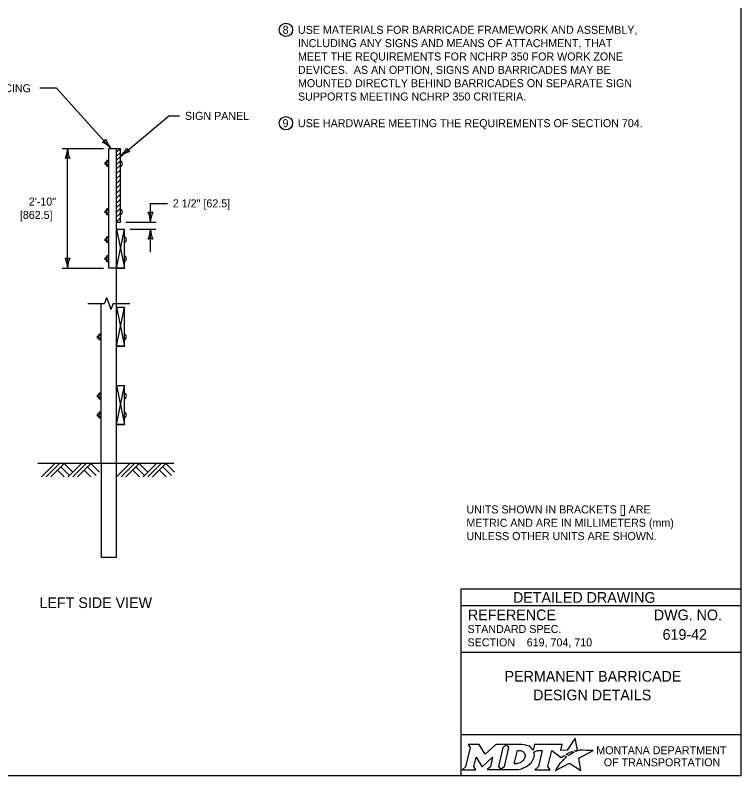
# Model space of a CAD drawing. Extents: x 49991.4 to 50021, y 49987.6 to 50011.4.
# Drawn here: x 50011.31 to 50016.75, y 49987.8 to 49993.5 of the extents above; entities that cross this region are included whole.
import ezdxf

# ---------------------------------------------------------------- set-up
doc = ezdxf.new("R2010")
doc.units = 0
for name, color, linetype in [('Default', 7, 'Continuous'), ('Level 1', 7, 'Continuous'), ('Level 2', 7, 'Continuous'), ('Level 3', 7, 'Continuous'), ('Level 4', 7, 'Continuous'), ('Level 5', 7, 'Continuous'), ('Level 6', 7, 'Continuous')]:
    doc.layers.add(name, color=color, linetype=linetype)

msp = doc.modelspace()

# ---------------------------------------------------------------- linework, layer by layer
at = {"layer": 'Default'}
for points in [[(50015.5126, 49987.9811), (50015.5023, 49987.9867), (50015.5139, 49987.9895), (50015.5255, 49987.9915), (50015.5081, 49988.0816), (50015.4486, 49987.9903), (50015.4013, 49987.9896), (50015.4116, 49988.0337), (50015.2024, 49988.0338), (50015.1923, 49987.9913), (50015.1865, 49987.9996)], [(50014.7056, 49988.0338), (50014.7197, 49988.0104), (50014.6862, 49987.8671), (50014.6605, 49987.8446), (50014.7621, 49987.8446), (50014.7486, 49987.8674), (50014.7648, 49987.9375), (50014.8085, 49987.8685), (50014.8138, 49987.8685), (50014.8889, 49987.938), (50014.8725, 49987.8669), (50014.8478, 49987.8449), (50014.9494, 49987.8449), (50014.9356, 49987.8682), (50014.9688, 49988.0106)], [(50014.9688, 49988.0106), (50014.9941, 49988.0338), (50014.9117, 49988.0338), (50014.8321, 49987.9608), (50014.7876, 49988.0335), (50014.7056, 49988.0338)], [(50015.1077, 49988.0338), (50014.9941, 49988.0338), (50015.0088, 49988.0109), (50014.9749, 49987.8671), (50014.9494, 49987.8449), (50015.06, 49987.8449)], [(50015.1317, 49987.9471), (50015.1305, 49987.939), (50015.1273, 49987.9297), (50015.1231, 49987.9215), (50015.1175, 49987.914), (50015.111, 49987.9071), (50015.1031, 49987.9008), (50015.0948, 49987.8961), (50015.0857, 49987.8922), (50015.0766, 49987.8899), (50015.0674, 49987.889), (50015.0515, 49987.889), (50015.0751, 49987.989), (50015.0911, 49987.989), (50015.0987, 49987.9884), (50015.1063, 49987.9865), (50015.1129, 49987.9835), (50015.119, 49987.9793), (50015.1238, 49987.9743), (50015.1275, 49987.9683), (50015.1302, 49987.9621), (50015.1318, 49987.9547), (50015.1318, 49987.9517), (50015.1317, 49987.9471)], [(50015.3882, 49987.8843), (50015.3729, 49987.8599), (50015.3682, 49987.8524), (50015.3624, 49987.8438), (50015.3601, 49987.8395), (50015.4654, 49987.8926), (50015.5493, 49987.8375), (50015.5362, 49987.9302), (50015.6431, 49987.9886), (50015.5938, 49987.9894), (50015.5637, 49987.9898), (50015.5429, 49987.9901), (50015.5361, 49987.9886), (50015.5312, 49987.9874), (50015.5228, 49987.9851), (50015.5126, 49987.9811)], [(50015.1991, 49987.9747), (50015.2237, 49987.9878), (50015.2606, 49987.9878), (50015.232, 49987.8673), (50015.2045, 49987.8446), (50015.3207, 49987.8446), (50015.3037, 49987.8675), (50015.3319, 49987.9877), (50015.4032, 49987.936), (50015.4243, 49987.9511), (50015.444, 49987.9402)], [(50015.4622, 49987.9535), (50015.4598, 49987.9518), (50015.4415, 49987.9614), (50015.4518, 49987.9671), (50015.4559, 49987.9693), (50015.4645, 49987.9733), (50015.4702, 49987.9759), (50015.4781, 49987.9789), (50015.4854, 49987.9816), (50015.4972, 49987.9742), (50015.4932, 49987.9721), (50015.4886, 49987.9696), (50015.4844, 49987.9674), (50015.4794, 49987.9645), (50015.4775, 49987.9634), (50015.4748, 49987.9618), (50015.4723, 49987.9604), (50015.47, 49987.9588), (50015.4674, 49987.957), (50015.4647, 49987.9552), (50015.4622, 49987.9535)], [(50015.4021, 49987.9004), (50015.4021, 49987.9004)], [(50015.1057, 49987.8522), (50015.1141, 49987.8548), (50015.1271, 49987.8602), (50015.1475, 49987.8712)]]:
    msp.add_lwpolyline(points, dxfattribs=at)
for centre, radius, start, end in [((50015.1308, 49987.9554), 0.0709, 339.5329, 15.8582), ((50015.0868, 49987.9727), 0.1183, 300.9103, 339.1383)]:
    msp.add_arc(centre, radius, start, end, dxfattribs=at)
for centre, major_axis, ratio, start_param, end_param in [((50015.1056, 49987.9864), (0.0834, -0.0037), 0.568097, 0.61298, 1.570796), ((50015.1612, 49987.9937), (0.0361, -0.0295), 0.469099, 1.225588, 1.570796), ((50015.4329, 49987.9305), (-0.0112, -0.0097), 0.021651, 3.157348, 6.283185), ((50015.3952, 49987.8923), (-0.00694, -0.00806), 0.008222, 0, 3.137361), ((50015.4119, 49987.9106), (-0.0098, -0.0102), 0.016458, 3.141593, 6.279097), ((50015.0603, 49987.9932), (0, 0.1484), 0.987302, 3.139398, 3.456847)]:
    msp.add_ellipse(centre, major_axis=major_axis, ratio=ratio, start_param=start_param, end_param=end_param, dxfattribs=at)
at = {"layer": 'Level 1'}
for p, q in [((50012.0102, 49992.5038), (50012.0975, 49992.5038)), ((50012.0102, 49991.6053), (50012.0102, 49992.5038)), ((50012.0687, 49991.8982), (50012.0687, 49992.5038)), ((50012.0975, 49992.5038), (50012.0687, 49992.475)), ((50012.0975, 49991.95), (50012.0975, 49992.5038)), ((50012.0975, 49992.4735), (50012.0687, 49992.4447)), ((50012.0975, 49992.4435), (50012.0687, 49992.4147)), ((50011.9838, 49992.3821), (50011.9838, 49992.3971)), ((50011.9952, 49992.3971), (50011.9838, 49992.3971)), ((50011.9952, 49992.3821), (50011.9838, 49992.3821)), ((50012.0102, 49992.4116), (50011.9952, 49992.4116)), ((50011.9952, 49992.3676), (50011.9952, 49992.4116)), ((50012.0102, 49992.4006), (50011.9952, 49992.4006)), ((50012.0975, 49992.4106), (50012.0687, 49992.3818)), ((50012.0102, 49992.3786), (50011.9952, 49992.3786)), ((50012.0102, 49992.3676), (50011.9952, 49992.3676)), ((50012.0975, 49992.3782), (50012.0687, 49992.3494)), ((50012.0975, 49992.3435), (50012.0687, 49992.3147)), ((50012.0975, 49992.3059), (50012.0687, 49992.2771)), ((50012.0975, 49992.2701), (50012.0687, 49992.2413)), ((50012.0975, 49992.2342), (50012.0687, 49992.2054)), ((50012.0975, 49992.1973), (50012.0687, 49992.1685)), ((50012.0975, 49992.1591), (50012.0687, 49992.1303)), ((50012.0975, 49992.1221), (50012.0687, 49992.0933)), ((50012.0102, 49992.0504), (50011.9952, 49992.0504)), ((50011.9952, 49992.0064), (50011.9952, 49992.0504)), ((50012.0102, 49992.0394), (50011.9952, 49992.0394)), ((50012.0975, 49992.0883), (50012.0687, 49992.0595)), ((50012.0975, 49992.054), (50012.0687, 49992.0252)), ((50011.9838, 49992.0209), (50011.9838, 49992.0359)), ((50011.9952, 49992.0359), (50011.9838, 49992.0359)), ((50011.9952, 49992.0209), (50011.9838, 49992.0209)), ((50012.0102, 49992.0174), (50011.9952, 49992.0174)), ((50012.0102, 49992.0064), (50011.9952, 49992.0064)), ((50012.0975, 49992.0183), (50012.0687, 49991.9895)), ((50012.0975, 49991.9827), (50012.0687, 49991.9539)), ((50012.0687, 49991.95), (50012.0975, 49991.95)), ((50012.0687, 49991.6053), (50012.1273, 49991.8982)), ((50012.0687, 49991.8982), (50012.1273, 49991.6053)), ((50012.0687, 49990.1408), (50012.0687, 49991.8982)), ((50012.0687, 49991.8982), (50012.1273, 49991.8982)), ((50012.1273, 49991.6053), (50012.1273, 49991.8982)), ((50011.9838, 49991.8112), (50011.9838, 49991.8262)), ((50011.9952, 49991.8262), (50011.9838, 49991.8262)), ((50011.9952, 49991.8112), (50011.9838, 49991.8112)), ((50012.0102, 49991.8407), (50011.9952, 49991.8407)), ((50011.9952, 49991.7967), (50011.9952, 49991.8407)), ((50012.0102, 49991.8297), (50011.9952, 49991.8297)), ((50012.0102, 49991.8077), (50011.9952, 49991.8077)), ((50012.0102, 49991.7967), (50011.9952, 49991.7967)), ((50012.0102, 49991.6972), (50011.9952, 49991.6972)), ((50011.9952, 49991.6532), (50011.9952, 49991.6972)), ((50011.9838, 49991.6677), (50011.9838, 49991.6827)), ((50011.9952, 49991.6827), (50011.9838, 49991.6827)), ((50011.9952, 49991.6677), (50011.9838, 49991.6677)), ((50012.0102, 49991.6862), (50011.9952, 49991.6862)), ((50012.0102, 49991.6642), (50011.9952, 49991.6642)), ((50012.0102, 49991.6532), (50011.9952, 49991.6532)), ((50012.1273, 49991.6053), (50012.0102, 49991.6053)), ((50012.0687, 49991.6053), (50012.1273, 49991.6053)), ((50011.9516, 49990.1408), (50011.9516, 49991.3405)), ((50012.0687, 49991.0195), (50012.1273, 49991.3124)), ((50012.0687, 49991.3124), (50012.1273, 49991.0195)), ((50012.0687, 49991.3124), (50012.1273, 49991.3124)), ((50012.1273, 49991.0195), (50012.1273, 49991.3124)), ((50011.9252, 49991.0813), (50011.9252, 49991.0963)), ((50011.9366, 49991.0963), (50011.9252, 49991.0963)), ((50011.9366, 49991.0813), (50011.9252, 49991.0813)), ((50011.9516, 49991.1108), (50011.9366, 49991.1108)), ((50011.9366, 49991.0668), (50011.9366, 49991.1108)), ((50011.9516, 49991.0998), (50011.9366, 49991.0998)), ((50011.9516, 49991.0778), (50011.9366, 49991.0778)), ((50011.9516, 49991.0668), (50011.9366, 49991.0668)), ((50012.1273, 49991.0195), (50012.0687, 49991.0195)), ((50012.0687, 49991.0195), (50012.1273, 49991.0195)), ((50012.0687, 49990.4336), (50012.1273, 49990.7265)), ((50012.0687, 49990.7265), (50012.1273, 49990.4336)), ((50012.0687, 49990.7265), (50012.1273, 49990.7265)), ((50012.1273, 49990.4336), (50012.1273, 49990.7265)), ((50011.9252, 49990.6385), (50011.9252, 49990.6535)), ((50011.9366, 49990.6535), (50011.9252, 49990.6535)), ((50011.9366, 49990.6385), (50011.9252, 49990.6385)), ((50011.9516, 49990.668), (50011.9366, 49990.668)), ((50011.9366, 49990.624), (50011.9366, 49990.668)), ((50011.9516, 49990.657), (50011.9366, 49990.657)), ((50011.9516, 49990.635), (50011.9366, 49990.635)), ((50011.9516, 49990.624), (50011.9366, 49990.624)), ((50011.9252, 49990.4954), (50011.9252, 49990.5104)), ((50011.9366, 49990.5104), (50011.9252, 49990.5104)), ((50011.9516, 49990.5249), (50011.9366, 49990.5249)), ((50011.9366, 49990.4809), (50011.9366, 49990.5249)), ((50011.9516, 49990.5139), (50011.9366, 49990.5139)), ((50011.9366, 49990.4954), (50011.9252, 49990.4954)), ((50011.9516, 49990.4919), (50011.9366, 49990.4919)), ((50011.9516, 49990.4809), (50011.9366, 49990.4809)), ((50012.1273, 49990.4336), (50012.0687, 49990.4336)), ((50012.0687, 49990.4336), (50012.1273, 49990.4336)), ((50012.4966, 49990.1408), (50011.4779, 49990.1408)), ((50011.5052, 49990.0408), (50011.6052, 49990.1408)), ((50011.5402, 49990.0408), (50011.6402, 49990.1408)), ((50011.5752, 49990.0408), (50011.6752, 49990.1408)), ((50011.6505, 49990.1161), (50011.7155, 49990.0511)), ((50011.6752, 49990.1408), (50011.7402, 49990.0758)), ((50011.7052, 49990.0408), (50011.8052, 49990.1408)), ((50011.7402, 49990.0408), (50011.8402, 49990.1408)), ((50011.7752, 49990.0408), (50011.8752, 49990.1408)), ((50011.8505, 49990.1161), (50011.9155, 49990.0511)), ((50011.8752, 49990.1408), (50011.9402, 49990.0758)), ((50012.0687, 49990.0407), (50012.1687, 49990.1407)), ((50012.1037, 49990.0407), (50012.2037, 49990.1407)), ((50012.1387, 49990.0407), (50012.2387, 49990.1407)), ((50012.214, 49990.116), (50012.279, 49990.051)), ((50012.2387, 49990.1407), (50012.3037, 49990.0757)), ((50012.2688, 49990.0408), (50012.3688, 49990.1408)), ((50012.3038, 49990.0408), (50012.4038, 49990.1408)), ((50012.3388, 49990.0408), (50012.4388, 49990.1408)), ((50012.4141, 49990.1161), (50012.4791, 49990.0511)), ((50012.4388, 49990.1408), (50012.5038, 49990.0758)), ((50011.6257, 49990.0913), (50011.6762, 49990.0408)), ((50011.8257, 49990.0913), (50011.8762, 49990.0408)), ((50012.1892, 49990.0912), (50012.2397, 49990.0407)), ((50012.3893, 49990.0913), (50012.4398, 49990.0408))]:
    msp.add_line(p, q, dxfattribs=at)
msp.add_lwpolyline([(49999.3835, 49998.9992), (50016.7501, 49998.9992), (50016.7501, 49987.7988), (49999.3835, 49987.7988)], close=True, dxfattribs=at)
for centre in [(50012.088, 49992.3889), (50012.088, 49992.0278), (50012.1178, 49991.8181), (50012.1178, 49991.6756), (50012.1178, 49991.0894), (50012.1178, 49990.6465), (50012.1178, 49990.5035)]:
    msp.add_arc(centre, 0.0243, 292.9563, 67.0437, dxfattribs=at)
at = {"layer": 'Level 2'}
for centre in [(50013.3387, 49993.3925), (50013.3387, 49992.6925)]:
    msp.add_circle(centre, 0.0501, dxfattribs=at)
at = {"layer": 'Level 3'}
for p, q in [((50011.6181, 49992.9543), (50011.4937, 49992.9543)), ((50011.6181, 49992.9543), (50012.0262, 49992.5038)), ((50012.0975, 49992.4435), (50012.4596, 49992.7475)), ((50012.4596, 49992.7475), (50012.5411, 49992.7475)), ((50011.6609, 49992.5038), (50011.9702, 49992.5038)), ((50011.7009, 49991.6053), (50011.7009, 49992.5038)), ((50012.3224, 49991.95), (50012.3224, 49992.0911)), ((50012.3224, 49992.0911), (50012.4504, 49992.0911)), ((50012.1375, 49991.95), (50012.3624, 49991.95)), ((50012.1673, 49991.8982), (50012.3624, 49991.8982)), ((50012.3224, 49991.7248), (50012.3224, 49991.8982)), ((50012.3224, 49991.8524), (50012.3224, 49991.8527)), ((50011.6609, 49991.6053), (50011.9702, 49991.6053))]:
    msp.add_line(p, q, dxfattribs=at)
for centre, radius, start, end in [((50011.9401, 49992.5988), 0.0548, 294.3092, 330.0315), ((50012.197, 49992.6461), 0.2223, 199.6264, 219.8099), ((50011.4788, 49992.513), 0.2223, 337.456, 357.6395), ((50011.9336, 49992.5153), 0.233, 182.8273, 202.0772), ((50011.8614, 49992.3391), 0.233, 44.9977, 64.2475), ((50011.939, 49992.6143), 0.233, 312.8587, 332.1085), ((50012.1957, 49992.526), 0.0548, 202.1702, 237.8926), ((50012.2334, 49992.2675), 0.2223, 107.4874, 127.6709), ((50011.7009, 49992.3756), 0.0548, 72.1388, 107.8612), ((50012.3224, 49992.0782), 0.0548, 252.1388, 287.8612), ((50012.0897, 49991.9385), 0.233, 2.8273, 22.0772), ((50012.5445, 49991.9408), 0.2223, 157.456, 177.6395), ((50012.1003, 49991.9074), 0.2223, 337.456, 357.6395), ((50012.5551, 49991.9097), 0.233, 182.8273, 202.0772), ((50012.3224, 49991.77), 0.0548, 72.1388, 107.8612), ((50011.7009, 49991.7335), 0.0548, 252.1388, 287.8612), ((50011.4682, 49991.5938), 0.233, 2.8273, 22.0772), ((50011.923, 49991.5961), 0.2223, 157.456, 177.6395)]:
    msp.add_arc(centre, radius, start, end, dxfattribs=at)
at = {"layer": 'Level 4'}
for p, q in [((50011.9516, 49990.1408), (50011.9516, 49989.4376)), ((50012.0687, 49989.4376), (50012.0687, 49990.1408)), ((50011.9516, 49989.4376), (50012.0687, 49989.4376))]:
    msp.add_line(p, q, dxfattribs=at)
at = {"layer": 'Level 5'}
for p, q in [((50016.7501, 49989.1988), (50014.6501, 49989.1988)), ((50014.6501, 49989.1988), (50014.6501, 49987.7988)), ((50016.7501, 49989.0738), (50014.6501, 49989.0738)), ((50016.3862, 49988.8587), (50016.3862, 49988.8587)), ((50015.1444, 49988.7993), (50015.1444, 49988.7993)), ((50016.7501, 49988.7238), (50014.6501, 49988.7238)), ((50015.7001, 49988.4747), (50015.7001, 49988.4747)), ((50016.7501, 49988.1057), (50014.6501, 49988.1057))]:
    msp.add_line(p, q, dxfattribs=at)
at = {"layer": 'Level 6'}
for p, q in [((50011.994, 49991.3862), (50011.9778, 49991.3405)), ((50011.994, 49991.3862), (50012.0102, 49991.3405)), ((50011.8516, 49991.3405), (50011.9778, 49991.3405)), ((50012.0102, 49991.3405), (50012.0264, 49991.2948)), ((50012.0426, 49991.3405), (50012.0264, 49991.2948)), ((50012.0426, 49991.3405), (50012.1687, 49991.3405))]:
    msp.add_line(p, q, dxfattribs=at)

# ---------------------------------------------------------------- texts
at = {"layer": 'Default'}
for s, p in [('MONTANA DEPARTMENT', (50015.6663, 49987.96)), ('OF TRANSPORTATION', (50015.7225, 49987.87))]:
    msp.add_text(s, height=0.06, dxfattribs=at).set_placement(p)
at = {"layer": 'Level 2'}
for s, height, p in [('8', 0.06, (50013.3135, 49993.3625)), ('USE MATERIALS FOR BARRICADE FRAMEWORK AND ASSEMBLY,', 0.06, (50013.4288, 49993.3625)), ('INCLUDING ANY SIGNS AND MEANS OF ATTACHMENT, THAT ', 0.06, (50013.4288, 49993.2625)), ('MEET THE REQUIREMENTS FOR NCHRP 350 FOR WORK ZONE', 0.06, (50013.4288, 49993.1625)), ('DEVICES.  AS AN OPTION, SIGNS AND BARRICADES MAY BE', 0.06, (50013.4288, 49993.0625)), ('MOUNTED DIRECTLY BEHIND BARRICADES ON SEPARATE SIGN', 0.06, (50013.4288, 49992.9625)), ('BACKBRACING', 0.06, (50010.8416, 49992.9243)), ('SUPPORTS MEETING NCHRP 350 CRITERIA.', 0.06, (50013.4288, 49992.8625)), ('SIGN PANEL', 0.06, (50012.5811, 49992.7175)), ('9', 0.06, (50013.3133, 49992.6625)), ('USE HARDWARE MEETING THE REQUIREMENTS OF SECTION 704.', 0.06, (50013.4288, 49992.6625)), ('2\'-10"', 0.06, (50011.4101, 49992.0746)), ('2 1/2" [62.5]', 0.06, (50012.4904, 49992.0611)), ('[862.5]', 0.06, (50011.343, 49991.9745)), ('UNITS SHOWN IN BRACKETS [] ARE ', 0.06, (50014.6921, 49989.766)), ('METRIC AND ARE IN MILLIMETERS (mm) ', 0.06, (50014.6921, 49989.666)), ('UNLESS OTHER UNITS ARE SHOWN.', 0.06, (50014.6921, 49989.566)), ('LEFT SIDE VIEW', 0.08, (50011.4904, 49989.0568)), ('619-42', 0.08, (50016.1636, 49988.8187)), ('619, 704, 710', 0.06, (50015.1444, 49988.7693)), ('PERMANENT BARRICADE', 0.08, (50014.9786, 49988.5047)), ('DESIGN DETAILS', 0.08, (50015.1925, 49988.3647))]:
    msp.add_text(s, height=height, dxfattribs=at).set_placement(p)
at = {"layer": 'Level 5'}
for s, height, p in [('DETAILED DRAWING', 0.0799, (50015.0418, 49989.0963)), ('REFERENCE', 0.08, (50014.7037, 49988.9654)), ('DWG. NO.', 0.08, (50016.0979, 49988.9654)), ('STANDARD SPEC.', 0.06, (50014.7004, 49988.8694)), ('SECTION', 0.06, (50014.7004, 49988.7694))]:
    msp.add_text(s, height=height, dxfattribs=at).set_placement(p)

doc.saveas('drawing.dxf')
